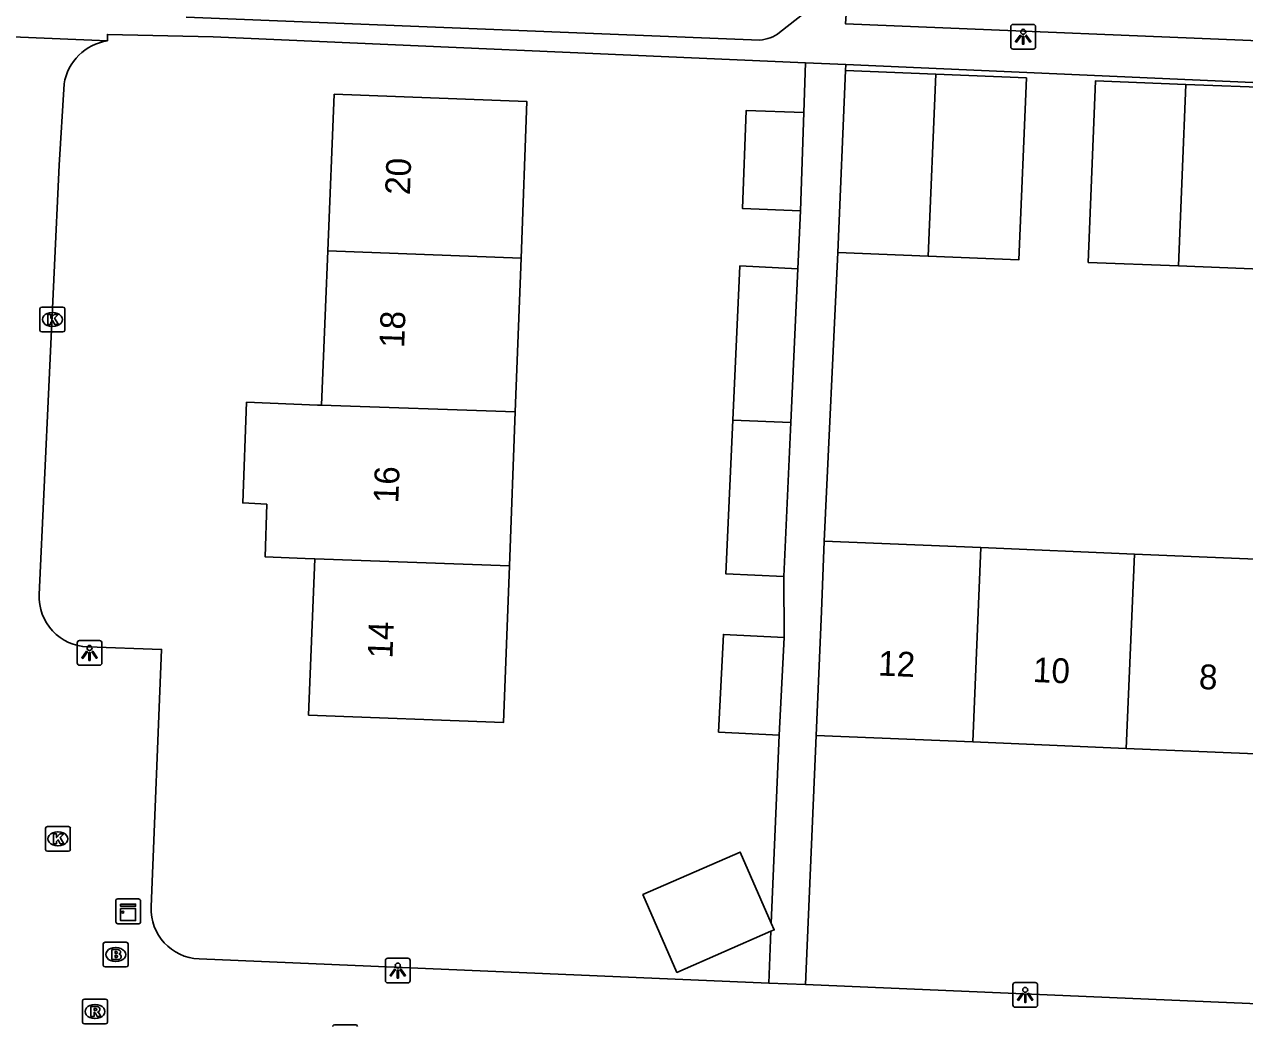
# Model space of a CAD drawing. Extents: x 160732 to 162105, y 387428 to 388479.
# Drawn here: x 161156.38 to 161205.54, y 387576.88 to 387617.29 of the extents above; entities that cross this region are included whole.
import ezdxf

# ---------------------------------------------------------------- set-up
doc = ezdxf.new("R2010")
doc.units = 0
for name, color, linetype in [('IMGEO_Brandkraan', 7, 'Continuous'), ('IMGEO_Kast', 7, 'Continuous'), ('IMGEO_Kolk', 7, 'Continuous'), ('IMGEO_Lichtpunt', 7, 'Continuous'), ('IMGEO_Pand', 7, 'Continuous'), ('IMGEO_Pand_nummerreeks', 7, 'Continuous'), ('IMGEO_Rioolput', 7, 'Continuous'), ('IMGEO_Voetpad_open', 7, 'Continuous')]:
    doc.layers.add(name, color=color, linetype=linetype)

msp = doc.modelspace()

# ---------------------------------------------------------------- linework, layer by layer
at = {"layer": 'IMGEO_Brandkraan'}
for p, q in [((161159.556, 387579.362), (161159.556, 387580.214)), ((161159.631, 387580.288), (161160.483, 387580.288)), ((161160.044, 387580.068), (161160.069, 387580.068)), ((161160.557, 387580.214), (161160.557, 387579.362)), ((161160.067, 387579.508), (161160.042, 387579.508)), ((161160.483, 387579.288), (161159.631, 387579.288))]:
    msp.add_line(p, q, dxfattribs=at)
for points in [[(161159.556, 387579.362), (161159.556, 387580.214)], [(161159.631, 387580.288), (161160.483, 387580.288)], [(161160.557, 387580.214), (161160.557, 387579.362)], [(161159.904, 387579.988), (161159.904, 387579.588), (161160.117, 387579.588)], [(161160.135, 387579.988), (161159.904, 387579.988)], [(161160.083, 387579.907), (161160.029, 387579.907), (161160.029, 387579.831)], [(161160.029, 387579.831), (161160.082, 387579.831)], [(161160.091, 387579.755), (161160.029, 387579.755), (161160.029, 387579.674)], [(161160.029, 387579.674), (161160.091, 387579.674)], [(161160.483, 387579.288), (161159.631, 387579.288)]]:
    msp.add_lwpolyline(points, dxfattribs=at)
for centre, radius, start, end in [((161159.633, 387580.212), 0.0765, 91.552, 178.448), ((161159.633, 387580.212), 0.0765, 91.552, 178.448), ((161160.481, 387580.212), 0.0765, 1.552, 88.448), ((161160.481, 387580.212), 0.0765, 1.552, 88.448), ((161160.084, 387579.869), 0.0379, 267.8285, 90.9355), ((161160.092, 387579.714), 0.0404, 269.8759, 90.5077), ((161160.123, 387579.839), 0.251, 268.6676, 293.5347), ((161160.139, 387579.843), 0.145, 59.4692, 91.5367), ((161160.164, 387579.89), 0.0922, 285.5137, 58.1501), ((161160.169, 387579.698), 0.105, 301.3115, 78.989), ((161159.633, 387579.364), 0.0765, 181.552, 268.448), ((161159.633, 387579.364), 0.0765, 181.552, 268.448), ((161160.481, 387579.364), 0.0765, 271.552, 358.448), ((161160.481, 387579.364), 0.0765, 271.552, 358.448)]:
    msp.add_arc(centre, radius, start, end, dxfattribs=at)
for centre, major_axis, ratio, start_param, end_param in [((161160.043, 387579.788), (-0.387, 0.002), 0.722429, 4.712389, 7.853982), ((161160.068, 387579.788), (-0.39, 0.002), 0.717154, 1.570796, 4.712389)]:
    msp.add_ellipse(centre, major_axis=major_axis, ratio=ratio, start_param=start_param, end_param=end_param, dxfattribs=at)
at = {"layer": 'IMGEO_Kast'}
for p, q in [((161160.136, 387582.03), (161160.977, 387582.03)), ((161160.977, 387582.03), (161160.136, 387582.03)), ((161160.061, 387581.105), (161160.061, 387581.946)), ((161160.061, 387581.946), (161160.061, 387581.105)), ((161161.061, 387581.955), (161161.061, 387581.114)), ((161161.061, 387581.114), (161161.061, 387581.955)), ((161160.986, 387581.03), (161160.145, 387581.03)), ((161160.145, 387581.03), (161160.986, 387581.03))]:
    msp.add_line(p, q, dxfattribs=at)
for points in [[(161160.256, 387581.82), (161160.856, 387581.82), (161160.856, 387581.735), (161160.256, 387581.735), (161160.256, 387581.82)], [(161160.256, 387581.645), (161160.856, 387581.645), (161160.856, 387581.156), (161160.256, 387581.156), (161160.256, 387581.645)]]:
    msp.add_lwpolyline(points, dxfattribs=at)
msp.add_circle((161160.34, 387581.494), 0.0377, dxfattribs=at)
for centre, start, end in [((161160.139, 387581.952), 92.4484, 184.2845), ((161160.139, 387581.952), 92.4484, 184.2845), ((161160.983, 387581.952), 2.4484, 94.2845), ((161160.983, 387581.952), 2.4484, 94.2845), ((161160.139, 387581.108), 182.4484, 274.2845), ((161160.139, 387581.108), 182.4484, 274.2845), ((161160.983, 387581.108), 272.4484, 4.2845), ((161160.983, 387581.108), 272.4484, 4.2845)]:
    msp.add_arc(centre, 0.0779, start, end, dxfattribs=at)
at = {"layer": 'IMGEO_Kolk'}
for p, q in [((161157.004, 387604.967), (161157.004, 387605.819)), ((161157.079, 387605.893), (161157.931, 387605.893)), ((161157.492, 387605.673), (161157.517, 387605.673)), ((161158.005, 387605.819), (161158.005, 387604.967)), ((161157.515, 387605.113), (161157.49, 387605.113)), ((161157.931, 387604.893), (161157.079, 387604.893)), ((161157.302, 387584.953), (161158.154, 387584.953)), ((161157.227, 387584.027), (161157.227, 387584.879)), ((161157.715, 387584.733), (161157.74, 387584.733)), ((161158.228, 387584.879), (161158.228, 387584.027)), ((161158.154, 387583.953), (161157.302, 387583.953)), ((161157.738, 387584.173), (161157.713, 387584.173)), ((161168.873, 387576.957), (161169.725, 387576.957))]:
    msp.add_line(p, q, dxfattribs=at)
for points in [[(161157.004, 387604.967), (161157.004, 387605.819)], [(161157.079, 387605.893), (161157.931, 387605.893)], [(161157.325, 387605.593), (161157.448, 387605.593), (161157.448, 387605.442), (161157.578, 387605.593), (161157.742, 387605.593), (161157.596, 387605.442), (161157.749, 387605.193), (161157.597, 387605.193), (161157.512, 387605.357), (161157.448, 387605.29), (161157.448, 387605.193), (161157.325, 387605.193), (161157.325, 387605.593)], [(161158.005, 387605.819), (161158.005, 387604.967)], [(161157.931, 387604.893), (161157.079, 387604.893)], [(161157.302, 387584.953), (161158.154, 387584.953)], [(161157.227, 387584.027), (161157.227, 387584.879)], [(161157.548, 387584.653), (161157.671, 387584.653), (161157.671, 387584.502), (161157.801, 387584.653), (161157.965, 387584.653), (161157.819, 387584.502), (161157.972, 387584.253), (161157.82, 387584.253), (161157.735, 387584.417), (161157.671, 387584.35), (161157.671, 387584.253), (161157.548, 387584.253), (161157.548, 387584.653)], [(161158.228, 387584.879), (161158.228, 387584.027)], [(161158.154, 387583.953), (161157.302, 387583.953)], [(161168.873, 387576.957), (161169.725, 387576.957)]]:
    msp.add_lwpolyline(points, dxfattribs=at)
for centre, start, end in [((161157.081, 387605.817), 91.552, 178.448), ((161157.081, 387605.817), 91.552, 178.448), ((161157.929, 387605.817), 1.552, 88.448), ((161157.929, 387605.817), 1.552, 88.448), ((161157.081, 387604.969), 181.552, 268.448), ((161157.081, 387604.969), 181.552, 268.448), ((161157.929, 387604.969), 271.552, 358.448), ((161157.929, 387604.969), 271.552, 358.448), ((161157.304, 387584.877), 91.552, 178.448), ((161157.304, 387584.877), 91.552, 178.448), ((161158.152, 387584.877), 1.552, 88.448), ((161158.152, 387584.877), 1.552, 88.448), ((161157.304, 387584.029), 181.552, 268.448), ((161157.304, 387584.029), 181.552, 268.448), ((161158.152, 387584.029), 271.552, 358.448), ((161158.152, 387584.029), 271.552, 358.448), ((161168.875, 387576.881), 91.552, 178.448), ((161168.875, 387576.881), 91.552, 178.448), ((161169.723, 387576.881), 1.552, 88.448), ((161169.723, 387576.881), 1.552, 88.448)]:
    msp.add_arc(centre, 0.0765, start, end, dxfattribs=at)
for centre, major_axis, ratio, start_param, end_param in [((161157.491, 387605.393), (-0.387, 0.002), 0.722429, 4.712389, 7.853982), ((161157.516, 387605.393), (-0.39, 0.002), 0.717154, 1.570796, 4.712389), ((161157.714, 387584.453), (-0.387, 0.002), 0.722429, 4.712389, 7.853982), ((161157.739, 387584.453), (-0.39, 0.002), 0.717154, 1.570796, 4.712389)]:
    msp.add_ellipse(centre, major_axis=major_axis, ratio=ratio, start_param=start_param, end_param=end_param, dxfattribs=at)
at = {"layer": 'IMGEO_Lichtpunt'}
for p, q in [((161196.121, 387617.195), (161196.121, 387616.388)), ((161196.121, 387617.195), (161196.121, 387616.388)), ((161197.023, 387617.29), (161196.215, 387617.29)), ((161197.023, 387617.29), (161196.215, 387617.29)), ((161197.117, 387616.388), (161197.117, 387617.195)), ((161197.117, 387616.388), (161197.117, 387617.195)), ((161196.215, 387616.294), (161197.023, 387616.294)), ((161196.215, 387616.294), (161197.023, 387616.294)), ((161158.504, 387592.353), (161158.504, 387591.546)), ((161158.504, 387592.353), (161158.504, 387591.546)), ((161159.406, 387592.448), (161158.598, 387592.448)), ((161159.406, 387592.448), (161158.598, 387592.448)), ((161159.5, 387591.546), (161159.5, 387592.353)), ((161159.5, 387591.546), (161159.5, 387592.353)), ((161158.598, 387591.452), (161159.406, 387591.452)), ((161158.598, 387591.452), (161159.406, 387591.452)), ((161170.922, 387579.547), (161170.922, 387578.74)), ((161170.922, 387579.547), (161170.922, 387578.74)), ((161171.824, 387579.642), (161171.016, 387579.642)), ((161171.824, 387579.642), (161171.016, 387579.642)), ((161171.918, 387578.74), (161171.918, 387579.547)), ((161171.918, 387578.74), (161171.918, 387579.547)), ((161171.016, 387578.646), (161171.824, 387578.646)), ((161171.016, 387578.646), (161171.824, 387578.646)), ((161196.203, 387578.567), (161196.203, 387577.76)), ((161196.203, 387578.567), (161196.203, 387577.76)), ((161197.105, 387578.662), (161196.297, 387578.662)), ((161197.105, 387578.662), (161196.297, 387578.662)), ((161197.199, 387577.76), (161197.199, 387578.567)), ((161197.199, 387577.76), (161197.199, 387578.567)), ((161196.297, 387577.666), (161197.105, 387577.666)), ((161196.297, 387577.666), (161197.105, 387577.666))]:
    msp.add_line(p, q, dxfattribs=at)
for points in [[(161196.495, 387616.859), (161196.534, 387616.831), (161196.346, 387616.569), (161196.308, 387616.596), (161196.495, 387616.859)], [(161196.597, 387616.811), (161196.644, 387616.811), (161196.644, 387616.489), (161196.597, 387616.489), (161196.597, 387616.811)], [(161196.707, 387616.831), (161196.745, 387616.858), (161196.932, 387616.596), (161196.893, 387616.568), (161196.707, 387616.831)], [(161158.878, 387592.017), (161158.917, 387591.989), (161158.729, 387591.727), (161158.691, 387591.754), (161158.878, 387592.017)], [(161158.98, 387591.969), (161159.027, 387591.969), (161159.027, 387591.647), (161158.98, 387591.647), (161158.98, 387591.969)], [(161159.09, 387591.989), (161159.128, 387592.016), (161159.315, 387591.754), (161159.276, 387591.726), (161159.09, 387591.989)], [(161171.296, 387579.211), (161171.335, 387579.183), (161171.147, 387578.921), (161171.109, 387578.948), (161171.296, 387579.211)], [(161171.398, 387579.163), (161171.445, 387579.163), (161171.445, 387578.841), (161171.398, 387578.841), (161171.398, 387579.163)], [(161171.508, 387579.183), (161171.546, 387579.21), (161171.733, 387578.948), (161171.694, 387578.92), (161171.508, 387579.183)], [(161196.577, 387578.231), (161196.616, 387578.203), (161196.428, 387577.941), (161196.39, 387577.968), (161196.577, 387578.231)], [(161196.679, 387578.183), (161196.726, 387578.183), (161196.726, 387577.861), (161196.679, 387577.861), (161196.679, 387578.183)], [(161196.789, 387578.203), (161196.827, 387578.23), (161197.014, 387577.968), (161196.975, 387577.94), (161196.789, 387578.203)]]:
    msp.add_lwpolyline(points, dxfattribs=at)
for centre in [(161196.62, 387616.993), (161159.003, 387592.151), (161171.421, 387579.345), (161196.702, 387578.365)]:
    msp.add_circle(centre, 0.0994, dxfattribs=at)
for centre, start, end in [((161196.215, 387617.195), 90, 180), ((161196.215, 387617.195), 90, 180), ((161197.023, 387617.195), 0, 90), ((161197.023, 387617.195), 0, 90), ((161196.215, 387616.388), 180, 270), ((161196.215, 387616.388), 180, 270), ((161197.023, 387616.388), 270, 0), ((161197.023, 387616.388), 270, 360), ((161158.598, 387592.353), 90, 180), ((161158.598, 387592.353), 90, 180), ((161159.406, 387592.353), 0, 90), ((161159.406, 387592.353), 0, 90), ((161158.598, 387591.546), 180, 270), ((161158.598, 387591.546), 180, 270), ((161159.406, 387591.546), 270, 0), ((161159.406, 387591.546), 270, 360), ((161171.016, 387579.547), 90, 180), ((161171.016, 387579.547), 90, 180), ((161171.824, 387579.547), 0, 90), ((161171.824, 387579.547), 0, 90), ((161171.016, 387578.74), 180, 270), ((161171.016, 387578.74), 180, 270), ((161171.824, 387578.74), 270, 0), ((161171.824, 387578.74), 270, 360), ((161196.297, 387578.567), 90, 180), ((161196.297, 387578.567), 90, 180), ((161197.105, 387578.567), 0, 90), ((161197.105, 387578.567), 0, 90), ((161196.297, 387577.76), 180, 270), ((161196.297, 387577.76), 180, 270), ((161197.105, 387577.76), 270, 0), ((161197.105, 387577.76), 270, 360)]:
    msp.add_arc(centre, 0.0946, start, end, dxfattribs=at)
at = {"layer": 'IMGEO_Pand'}
for points in [[(161189.15, 387608.1), (161189.459, 387615.438)], [(161189.459, 387615.438), (161193.105, 387615.285)], [(161192.797, 387607.946), (161193.105, 387615.285)], [(161193.105, 387615.285), (161196.75, 387615.132), (161196.441, 387607.793), (161192.797, 387607.946)], [(161202.882, 387607.55), (161199.244, 387607.693), (161199.532, 387615.015), (161203.169, 387614.872)], [(161168.604, 387608.157), (161168.86, 387614.475), (161176.626, 387614.182), (161176.387, 387607.863)], [(161202.882, 387607.55), (161203.169, 387614.872)], [(161203.169, 387614.872), (161206.807, 387614.729), (161206.52, 387607.407), (161202.882, 387607.55)], [(161187.642, 387609.78), (161185.314, 387609.862), (161185.452, 387613.817), (161187.78, 387613.736)], [(161187.78, 387613.736), (161187.642, 387609.78)], [(161168.353, 387601.933), (161168.512, 387605.877), (161168.604, 387608.157)], [(161168.604, 387608.157), (161176.387, 387607.863)], [(161192.797, 387607.946), (161189.15, 387608.1)], [(161176.387, 387607.863), (161176.153, 387601.665)], [(161184.923, 387601.333), (161185.208, 387607.555), (161187.543, 387607.442)], [(161187.543, 387607.442), (161187.259, 387601.244)], [(161168.081, 387595.74), (161167.689, 387595.757), (161166.072, 387595.828), (161166.145, 387597.944), (161165.172, 387597.997), (161165.33, 387602.055), (161168.192, 387601.94), (161168.353, 387601.933)], [(161168.353, 387601.933), (161176.153, 387601.665)], [(161176.153, 387601.665), (161175.92, 387595.467)], [(161186.975, 387595.031), (161184.64, 387595.138), (161184.923, 387601.333)], [(161184.923, 387601.333), (161187.259, 387601.244)], [(161187.259, 387601.244), (161186.975, 387595.031)], [(161188.277, 387588.624), (161188.487, 387593.62), (161188.607, 387596.46)], [(161188.607, 387596.46), (161194.915, 387596.194)], [(161175.92, 387595.467), (161175.681, 387589.149), (161167.827, 387589.445), (161168.081, 387595.74)], [(161168.081, 387595.74), (161175.92, 387595.467)], [(161194.915, 387596.194), (161194.585, 387588.359)], [(161194.915, 387596.194), (161201.105, 387595.934)], [(161200.775, 387588.098), (161201.105, 387595.934)], [(161201.105, 387595.934), (161207.295, 387595.673)], [(161186.792, 387588.632), (161184.346, 387588.755), (161184.544, 387592.696), (161186.99, 387592.573)], [(161186.99, 387592.573), (161186.792, 387588.632)], [(161194.585, 387588.359), (161188.277, 387588.624)], [(161200.775, 387588.098), (161194.585, 387588.359)], [(161206.965, 387587.838), (161200.775, 387588.098)], [(161186.471, 387581.054), (161185.22, 387583.917), (161181.301, 387582.205), (161182.671, 387579.071), (161186.457, 387580.725)], [(161186.457, 387580.725), (161186.589, 387580.783), (161186.471, 387581.054)]]:
    msp.add_lwpolyline(points, dxfattribs=at)
at = {"layer": 'IMGEO_Rioolput'}
for p, q in [((161158.721, 387577.066), (161158.721, 387577.918)), ((161158.796, 387577.992), (161159.648, 387577.992)), ((161159.209, 387577.772), (161159.234, 387577.772)), ((161159.722, 387577.918), (161159.722, 387577.066)), ((161159.232, 387577.212), (161159.207, 387577.212)), ((161159.648, 387576.992), (161158.796, 387576.992))]:
    msp.add_line(p, q, dxfattribs=at)
for points in [[(161158.721, 387577.066), (161158.721, 387577.918)], [(161158.796, 387577.992), (161159.648, 387577.992)], [(161159.31, 387577.69), (161159.058, 387577.692), (161159.058, 387577.292)], [(161159.236, 387577.611), (161159.182, 387577.611), (161159.182, 387577.53)], [(161159.722, 387577.918), (161159.722, 387577.066)], [(161159.058, 387577.292), (161159.182, 387577.292), (161159.182, 387577.454), (161159.193, 387577.454)], [(161159.182, 387577.53), (161159.234, 387577.53)], [(161159.24, 387577.425), (161159.311, 387577.292), (161159.451, 387577.292), (161159.386, 387577.418)], [(161159.648, 387576.992), (161158.796, 387576.992)]]:
    msp.add_lwpolyline(points, dxfattribs=at)
for centre, radius, start, end in [((161158.798, 387577.916), 0.0765, 91.552, 178.448), ((161158.798, 387577.916), 0.0765, 91.552, 178.448), ((161159.242, 387577.515), 0.0964, 77.0061, 93.1865), ((161159.256, 387577.572), 0.0378, 276.6634, 79.6772), ((161159.309, 387577.58), 0.109, 350.3612, 89.416), ((161159.307, 387577.58), 0.112, 277.5842, 350.9817), ((161159.646, 387577.916), 0.0765, 1.552, 88.448), ((161159.646, 387577.916), 0.0765, 1.552, 88.448), ((161158.798, 387577.068), 0.0765, 181.552, 268.448), ((161158.798, 387577.068), 0.0765, 181.552, 268.448), ((161159.192, 387577.401), 0.0533, 26.0293, 88.6989), ((161159.218, 387577.719), 0.19, 274.7715, 282.9687), ((161159.291, 387577.365), 0.108, 29.5134, 73.7905), ((161159.646, 387577.068), 0.0765, 271.552, 358.448), ((161159.646, 387577.068), 0.0765, 271.552, 358.448)]:
    msp.add_arc(centre, radius, start, end, dxfattribs=at)
for centre, major_axis, ratio, start_param, end_param in [((161159.208, 387577.492), (-0.387, 0.002), 0.722429, 4.712389, 7.853982), ((161159.233, 387577.492), (-0.39, 0.002), 0.717154, 1.570796, 4.712389)]:
    msp.add_ellipse(centre, major_axis=major_axis, ratio=ratio, start_param=start_param, end_param=end_param, dxfattribs=at)
at = {"layer": 'IMGEO_Voetpad_open'}
for points in [[(161234.447, 387616.696), (161234.394, 387615.505), (161208.407, 387616.534), (161189.465, 387617.313), (161189.538, 387618.499)], [(161188.284, 387618.125), (161186.802, 387616.961)], [(161186.008, 387616.661), (161162.899, 387617.576)], [(161159.724, 387616.629), (161159.724, 387616.888), (161163.977, 387616.793), (161187.85, 387615.74)], [(161154.925, 387616.832), (161159.724, 387616.629)], [(161187.85, 387615.74), (161187.78, 387613.736)], [(161187.85, 387615.74), (161189.469, 387615.669)], [(161189.459, 387615.438), (161189.469, 387615.669)], [(161189.469, 387615.669), (161226.827, 387614.021)], [(161157.98, 387614.894), (161157.782, 387611.62), (161156.977, 387594.302)], [(161187.642, 387609.78), (161187.543, 387607.442)], [(161188.607, 387596.46), (161189.15, 387608.1)], [(161186.975, 387595.031), (161186.99, 387592.573)], [(161158.931, 387592.191), (161161.907, 387592.091), (161161.483, 387581.709)], [(161186.792, 387588.632), (161186.471, 387581.054)], [(161187.85, 387578.575), (161188.277, 387588.624)], [(161186.457, 387580.725), (161186.368, 387578.638)], [(161163.415, 387579.613), (161186.368, 387578.638)], [(161186.368, 387578.638), (161187.85, 387578.575)], [(161187.85, 387578.575), (161225.228, 387576.988)]]:
    msp.add_lwpolyline(points, dxfattribs=at)
for centre, radius, start, end in [((161185.921, 387618.092), 1.434, 273.4789, 307.9176), ((161160.05, 387614.557), 2.098, 98.953, 170.7506), ((161158.998, 387594.213), 2.023, 177.4691, 268.1073), ((161163.497, 387581.627), 2.016, 177.6794, 267.6576)]:
    msp.add_arc(centre, radius, start, end, dxfattribs=at)

# ---------------------------------------------------------------- texts
at = {"layer": 'IMGEO_Pand_nummerreeks'}
for s, rotation, p in [('20', 87.8402, (161171.909, 387610.401)), ('18', 87.8402, (161171.677, 387604.234)), ('16', 87.8402, (161171.44, 387597.973)), ('14', 87.8402, (161171.204, 387591.715)), ('12', 357.5902, (161190.761, 387591.041)), ('10', 357.5902, (161196.996, 387590.779)), ('8', 357.5902, (161203.686, 387590.498))]:
    msp.add_text(s, height=1, rotation=rotation, dxfattribs=at).set_placement(p)

doc.saveas('drawing.dxf')
